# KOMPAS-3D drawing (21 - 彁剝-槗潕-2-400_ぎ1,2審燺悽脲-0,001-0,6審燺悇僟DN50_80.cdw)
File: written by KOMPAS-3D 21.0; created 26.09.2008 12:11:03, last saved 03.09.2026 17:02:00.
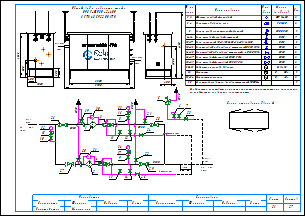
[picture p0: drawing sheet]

Sheets 1-2: A3, landscape

Document properties: Наименование: Макро:21; Автор: RaskoAdmin; Форматы листов документа: 2xA3; Полное имя файла: \\UR38nt01\Departments\КТО\КБ ПУРДГ\Заявки\Прайс-лист на типовые шкафы ГРПШ\ПРДГ_стандарт_20_03_2026\ПРДГ с РДГ(Н, В)\ПРДГ-ШУЭО-2-400_до1,2МПа_Рвых-0,001-0,6МПа_РДГ_DN50_80.cdw

Title block, sheet 1: Наименование: Пункт учета газа / ПУГ-Ш-400-Р / ЛГТИ.485922.001ТУ; designation: ЛГТИ.03.4411141; sheet number: 1; Количество листов документа: 2; organisation: ООО "ЭЛЬСТЕР Газэлектроника"; Форматы листов документа: A3; stored path: C:\Рабочие документы\Компас\ПУГ\Схема.cdw; Разработал: Устинов; Проверил: Кошкин; Утвердил: Кошкин
Title block, sheet 2: sheet number: 2; stored path: D:\Рабочие документы\Заявки\ПУРДГ\ПУРДГ-ШУЭО-2-100-Р 4411220.cdw; designation, second copy: ЛГТИ.03.4411141-

Views: Вид 1, Вид 2
Referenced files: wcvoit.frw
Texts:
  Normal
  № на
  схеме
  Усл.
  обозн.
  Марка
  (модель)
  Кол.
  Фильтр газовый фланцевый
  ФГ 16-50
  Регулятор давления газа
  РДГ-50
  Клапан предохранительный сбросной
  КПС DN20
  Кран шаровой газовый латунный
  DN15
  Кран кнопочный VE-РАСКО-НЗ-1,6-G1/2-М20
  Кран шаровой "под приварку" штуцерный DN20 PN16
  Кран шаровой "под приварку" штуцерный п/п DN20 PN16
  DN20
  Кран шаровой фланцевый DN50 PN16
  Кран шаровой фланцевый DN80 PN16
  DN50
  DN80
  Индикатор перепада давления
  Delta 15
  Манометр
  Манометр-напоромер
  Электрообогреватель взрывозащищенный 1000Вт
  0...     МПа
  0...     кПа
  Общий вид и габариты шкафа
  ПРДГ-ШУЭО-2-400
  Выход газа
  Вход газа
  logo-rasko-ge.png
  Вход
  газа
  PDI
  Выход
  Р=     кПа
  Импульс DN20
  ≥5DN
  HYSWLongFangSong
  Р=       МПа
  Схема открывания дверей
  Предприятие изготовитель может заменять комплектующие на аналогичные,
  не ухудшающие заявленных характеристик.
  Должность
  Конструктор
  Фамилия
  Подпись
  Дата
  Согласовано
  Максимкин
  Лист
  Листов
  POLYLINE_STYLE_0.18_RGB_0_0_0
  POLYLINE_STYLE_0.50_RGB_0_0_0
  POLYLINE_STYLE_0.34_RGB_0_0_0
  PHANTOM_RGB_0_0_0_SC_1_THICK_0.18
  K5LT_THIN_RGB_0_0_0_THICK_0.18
  K5LT32769_RGB_0_0_0_THICK_0.18
  K5LT12_RGB_0_0_0_SC_1_THICK_0.18
  K5LT_DASHED_RGB_0_0_0_SC_1_THICK_0.18
  ACISOTGL_RGB_0_0_0_SC_0.8_THICK_0.25
  CONTINUOUS_RGB_0_127_31_THICK_0.3
  CONTINUOUS_RGB_0_0_255_THICK_0.35
  CONTINUOUS_RGB_255_0_0_THICK_0.35
  POLYLINE_STYLE_0.25_RGB_0_0_0
  CONTINUOUS_RGB_0_0_0_THICK_0.5
  POLYLINE_STYLE_0.35_RGB_0_0_255
  CONTINUOUS_RGB_0_0_0_THICK_0.4
  CONTINUOUS_RGB_0_0_0_THICK_0.35
  Без оформления
Dimensions and other numbers on the sheet: 1; 1, 2; 2; 3, 4; 5; 6-14; 9; 15-17; 3; 18-23; 24-25; 6; 26-27; 28-29; 30-31; 32; 33-34; 35; 400; 1050; 500; 305; 1565; 3100; 1000; 4130; 2800; 4; 10; 27; 28; 29; 23; 8; 12; 19; 20; 21; 22; 25; 24; 30; 31; 15; 16; 26; 7; 11; 14; 13; 33; 17; 34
